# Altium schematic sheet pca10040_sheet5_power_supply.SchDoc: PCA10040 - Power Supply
size A4; Revision: 1.1.0; SheetNumber: 5; SheetTotal: 5; DrawnBy: KJP; ProjectNumber: 4397; PCBRevision: 0071KJP; DocumentSize: A4; PCAName: PCA10040; PCBNumber: 400150
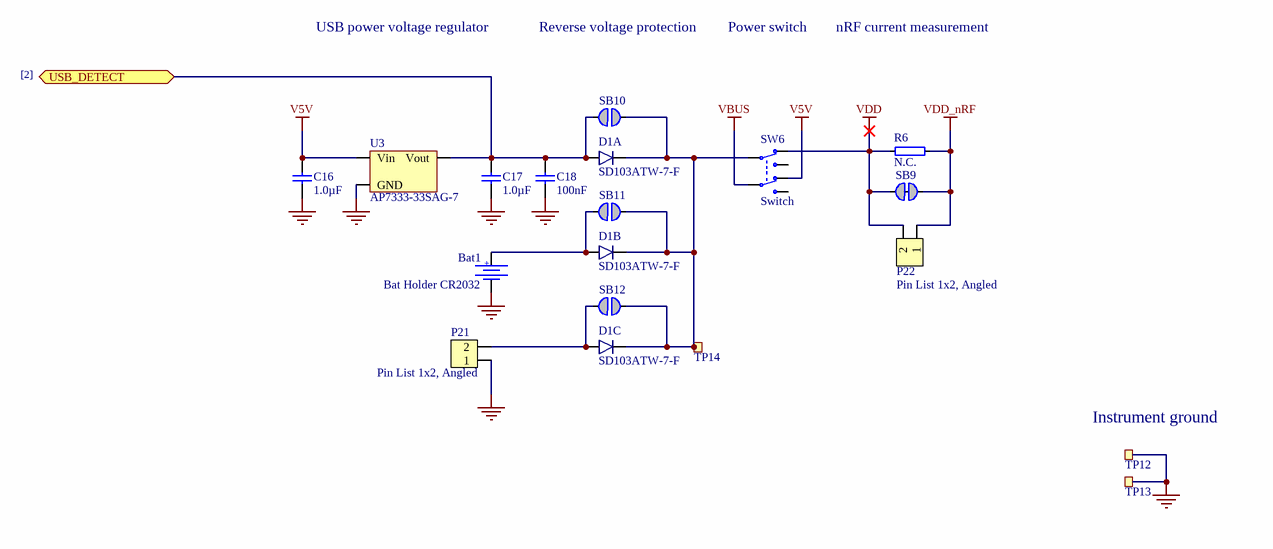
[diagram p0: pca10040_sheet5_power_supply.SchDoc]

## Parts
Bat1  Bat Holder CR2032  [CR2032_HOLDER_SMD]
C16  1.0µF  [CAPC1608X06L]
C17  1.0µF  [CAPC1608X06L]
C18  100nF  [CAPC1005X04L]
D1  SD103ATW-7-F  [SOT-363]  (parts A,B,C of 3)
P21  Pin List 1x2, Angled  [LIST_ANG_1x2-SMD-2.54MM]
P22  Pin List 1x2, Angled  [LIST_ANG_1x2-SMD-2.54MM]
R6  N.C.  [RESC1005X04L]
SB9  Solderbridge  [Solderbridge_Shorted]  (value not drawn)  (net tie, no BOM)
SB10  Solderbridge  [Solderbridge]  (value not drawn)  (no BOM)
SB11  Solderbridge  [Solderbridge]  (value not drawn)  (no BOM)
SB12  Solderbridge  [Solderbridge]  (value not drawn)  (no BOM)
SW6  Switch  [JS202011SCQN]
TP12  TP  [TESTPAD-TH]  (value not drawn)  (no BOM)
TP13  TP  [TESTPAD-TH]  (value not drawn)  (no BOM)
TP14  Ø1.0mm,SMD  [TP_SMD_Ø1.0mm]  (value not drawn)  (no BOM)
U3  AP7333-33SAG-7  [SOT-23A]

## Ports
USB_DETECT (bidir)

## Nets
GND: Bat1.2 C16.1 C17.1 C18.1 P21.1 TP12.1 TP13.1 U3.3(GND)
V5V: C16.2 SW6.6(N.C-2) U3.1(Vin)
VBUS: SW6.5(COM-2)
VDD: P22.2 R6.1 SB9.2 SW6.3(N.C-1)
VDD_nRF: P22.1 R6.2 SB9.1
USB_DETECT: C17.2 C18.2 D1.6(A1) SB10.2 U3.2(Vout) ; port USB_DETECT
NetBat1_1: Bat1.1 D1.5(A2) SB11.2
NetD1_1: D1.1(C1) D1.2(C2) D1.3(C3) SB10.1 SB11.1 SB12.1 SW6.2(COM-1) TP14.1
NetD1_4: D1.4(A3) P21.2 SB12.2

Not connected (* = marked no-connect by the designer): SW6 1(N.O-1) 4(N.O-2)

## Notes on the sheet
- USB power voltage regulator
- Reverse voltage protection
- Power switch
- nRF current measurement
- [2]
- (near TP12) Instrument ground

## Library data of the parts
Bat1 = Bat Holder CR2032 SMD: Manufacturer: Keystone; Manufacturer Part Number: 3002; 2nd source part number: 69-525-27; Artikkelnr Noca: 34019038; Artikkelnr Simpro: N.A.
C16 C17 = C0603-1µ0: Capacitor, X7R, ±10%; Note: 16V; Artikkelnr Noca: 20039335; Artikkelnr Simpro: N.A.
C18 = C0402-100n: Capacitor, X7R, ±10%; Note: 16V; Artikkelnr Noca: 20039200; Artikkelnr Simpro: N.A.
D1 = SD103ATW-7-F: Surface Mount Schottky Barrier Diode Array; Manufacturer: Diodes Incorporated; 2nd source part number: 177-3507; Artikkelnr Noca: 10029109; Artikkelnr Simpro: N.A.
P21 P22 = Pin List Ang 1x2 SMD, 2.54mm: Pin List 1x2, 2.54mm (100mil), Right Angled, SMD; Manufacturer: Cabcon; Manufacturer Part Number: 1125B-1102S3Z120R2; 2nd source part number: TSM-102-01-L-SH-A; Artikkelnr Noca: 55010008; Artikkelnr Simpro: N.A.
R6 = R0402-N.C.: Not mounted; Note: Chip Res; Artikkelnr Noca: N.A.
SB9 = Solderbridge Shorted: Shorted Solderbridge; Artikkelnr Noca: N.A.
SB10-SB12 = Solderbridge: Artikkelnr Noca: N.A.
SW6 = JS202011SCQN: SMD slide Switch (ON-ON); Manufacturer: C&K Components; 2nd source part number: 232-0019; Artikkelnr Noca: N.A.
TP12 TP13 = Testpoint TH: Testpoint, through hole; Artikkelnr Noca: N.A.
TP14 = TP_SMD_Ø1.0MM: 1.0mm circular SMD testpad; Manufacturer: Nordic Semiconductor; Artikkelnr Noca: N.A.
U3 = AP7333-33SAG-7: 300mA, Low Quiescent Current, Fast Transient Low Dropout Linear Regulator; Manufacturer: Diodes Incorporated; Artikkelnr Noca: 17039216; Artikkelnr Simpro: N.A.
